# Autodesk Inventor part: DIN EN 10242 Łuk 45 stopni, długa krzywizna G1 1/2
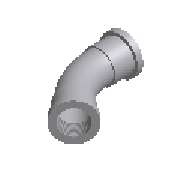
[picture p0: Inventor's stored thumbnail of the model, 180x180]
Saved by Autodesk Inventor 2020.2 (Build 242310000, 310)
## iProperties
Manager: www.cadconsulting.pl
Company: Fabian Stasiak CAD Consulting
Created: 2014-02
Part Number: DIN EN 10242 Łuk 45 stopni, długa krzywizna G1 1/2
Material: Żelazo, ciągliwe
Description: Gięcie
Document SubType Name: Modeling
Standard: DIN EN 10242
Designer: F.Stasiak
Standards Organization: DIN
Language: pl-PL
Size Designation: 1/2
Categories: <MemberInstance><Categories><Category DisplayName="Rury cienko- i grubościenne" InternalName="4347fa0f-2144-441d-94cd-e3e15c92b736" Mnemonic="TUBEANDPIPE"><Cate
Density: 7.15 g/cm^3
Appearance: Częściowo polerowana
Catalog Web Link: www.expertbooks.pl
NAME: PIPING: DIN EN 10242 45 Deg Long Sweep Bend G1
DATA: <meta><inlinegroups number="0" deflen="0"></inlinegroups><connections number="2"></connections><angles><a>2.35619449019234</a></angles></meta>
IsCustomPart: 0
Author: F.Stasiak
Subject: Zbiór ćwiczeń. Autodesk Inventor 2020. Kurs Professional
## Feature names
1. Revolution1
2. Revolution2
3. Sweep1
## Parameters: a = 36 mm, MD = 18.631 mm, H = 28.21 mm, d0 = 18.631 mm, d1 = 28.21 mm, d2 = 4.34 mm, d3 = 19.5 mm, d26 = 90 deg, d4 = 18.631 mm, d5 = 23.87 mm, d6 = 28.21 mm, d7 = 4.34 mm, d8 = 19.5 mm, d37 = 90 deg, EE = 4.34 mm, D = 21.7 mm, z = 23 mm, d9 = 23.87 mm, d10 = 0, d15 = 13 mm, d16 = 21.7 mm, d17 = 36 mm, d18 = 45 deg, d19 = 36 mm, d20 = 13 mm, d99 = 13 mm, d100 = 0, d101 = 13 mm, d102 = 0, d103 = 0, Size_Designation = 5 mm
